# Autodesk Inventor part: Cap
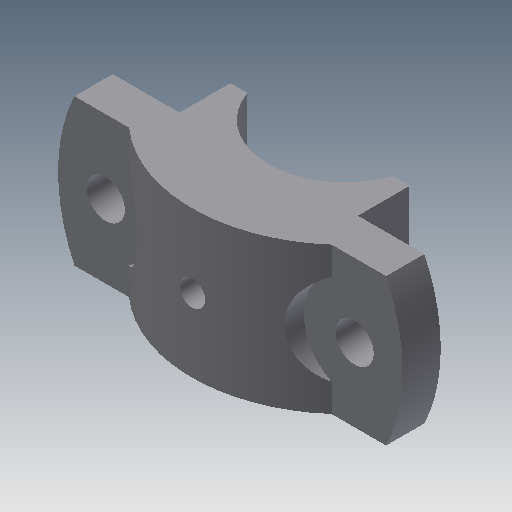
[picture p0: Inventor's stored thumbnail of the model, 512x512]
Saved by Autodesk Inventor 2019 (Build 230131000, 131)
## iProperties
Created: 2009-04
Part Number: Cap
Document SubType Name: Modeling
Designer: Sham
Density: 1 g/cm^3
Material: Generic
Appearance: Default
Author: Sham
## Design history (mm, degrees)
sketch "Sketch1"
  geometry: L1 (-48.857, 23)-(48.857, 23); L2 (48.857, -23)-(-48.857, -23); A1 r 54 centre (0, 0) between (-48.857, 23) and (-48.857, -23); A2 r 54 centre (0, 0) between (48.857, -23) and (48.857, 23); 1 further point
  constraints: 4 end point, 4 point on circle, 2 centre point, 2 coincident, 1 horizontal, 1 parallel, 1 other
  dimensions: "d3" = 54 radius of A1; "d4" = 54 radius of A2; "d5" = 46 distance between parallel lines of L2 L1; "d6" = 23 distance from line of point (0, 0) L1
extrude "Extrusion1" new body sketch "Sketch1" distance "d7" = 12; taper "d8" = 0 deg
sketch "Sketch3"
  geometry: L1 (20.906, 0)-(20.906, -16); L2 (76.906, -0.137)-(76.906, -16.137); L3 (20.906, -16)-(26.23, -16); L4 (71.532, -16.137)-(76.906, -16.137); L5 (76.906, -0.137)-(76.857, 12); L6 (97.714, 0)-(0, 0) reference; L7 (76.857, 12)-(80.606, 12); L8 (17.108, 12)-(20.906, 12); L9 (20.906, 12)-(20.906, 0); L10 (0, 12)-(97.714, 12) reference; A1 r 24 centre (48.857, -24) between (71.532, -16.137) and (26.23, -16); A2 r 48 centre (48.857, -24) between (80.606, 12) and (17.108, 12); 3 further points
  constraints: 16 end point, 4 point on circle, 3 parallel, 3 perpendicular, 2 centre point, 2 coincident, 2 vertical alignment, 1 collinear, 1 midpoint, 1 vertical, 2 other
  dimensions: "d17" = 48 diameter of A1; "d18" = 16 distance of L1.start L1.end; "d19" = 56 distance between parallel lines of L2 L1; "d21" = 8 vertical distance of A1.centre L1.end; "d22" = 48 radius of A2; "d23" = 0 distance from line of L6 L1.start; "d38" = 31.74902 distance of L7.end point (48.857, 12); "d39" = 28 distance from line of point (48.857, 12) L5
extrude "Extrusion2" join sketch "Sketch3" stored distance "d24" = 12; taper "d25" = 0 deg
sketch "Sketch4"
  geometry: 2 further points
  dimensions: "d26" = 78 distance of point (39, 0) point (-39, 0)
hole "Hole1" sketch "Sketch4" at (-39, 0), (39, 0) diameter "d28" = 12; stored, may be unused: countersink angle "d32" = 90 deg, drill point angle "d34" = 118 deg; dims "d29" = 6, "d30" = 4, "d31" = 2, "d33" = 8
sketch "Sketch5"
  geometry: L1 (-31.749, -23)-(-31.749, 23) reference; L2 (-31.749, 14.263)-(-31.749, -14.263); C1 r 6 at (-39, 0) reference; A1 r 16 centre (-39, 0) between (-31.749, -14.263) and (-31.749, 14.263)
  constraints: 2 end point, 2 point on circle, 1 centre point, 1 coincident, 1 collinear, 1 point on line
  dimensions: "d35" = 16 radius of A1
extrude "Extrusion3" cut sketch "Sketch5" distance "d36" = 12; taper "d37" = 0 deg
mirror "Mirror2"
workplane "Work Plane4"
sketch "Sketch6"
  geometry: L1 (-31.749, 0)-(31.749, 0) reference; 1 further point
  dimensions: "d40" = 23 distance from line of L1 point (0, 23)
hole "Hole2" sketch "Sketch6" at (0, 23) diameter "d41" = 6; stored, may be unused: countersink angle "d45" = 90 deg, drill point angle "d47" = 118 deg; dims "d42" = 6, "d43" = 8, "d44" = 16, "d46" = 8
body "Solid1"
